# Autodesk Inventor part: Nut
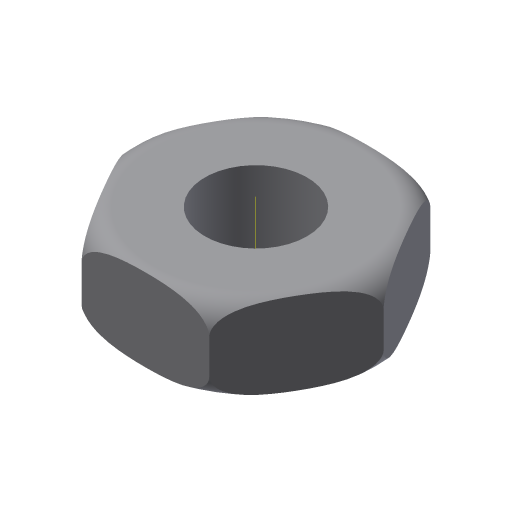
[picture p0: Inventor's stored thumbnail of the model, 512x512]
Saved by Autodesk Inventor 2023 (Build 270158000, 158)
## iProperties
Created: 2009-04
Part Number: Nut
Document SubType Name: Modeling
Designer: Sham
Density: 1 g/cm^3
Material: Generic
Appearance: Default
Author: Sham
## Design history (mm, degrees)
sketch "Sketch1"
  geometry: L1 (7.5, 12.99)-(15, 0); L2 (15, 0)-(7.5, -12.99); L3 (7.5, -12.99)-(-7.5, -12.99); L4 (-7.5, -12.99)-(-15, 0); L5 (-15, 0)-(-7.5, 12.99); L6 (-7.5, 12.99)-(7.5, 12.99); C1 r 6 at (0, 0); 1 further point
  constraints: 12 end point, 1 centre point, 1 coincident, 13 other
  dimensions: "d0" = 30 distance of L1.end L4.end; "d1" = 12 diameter of C1
extrude "Extrusion1" new body sketch "Sketch1" distance "d2" = 12; taper "d3" = 0 deg
sketch "Sketch2"
  geometry: L1 (-12, 0)-(-12, -0.022); L2 (-15, 7)-(-15, 3); L3 (0, -2.87)-(0, 12.87) reference; A1 r 3 centre (-12, 7) between (-12, 10) and (-15, 7); A2 r 3 centre (-12, 3) between (-15, 3) and (-12, 0)
  constraints: 4 end point, 4 point on circle, 2 centre point, 1 tangent
revolve "Revolution1" sketch "Sketch2" stored, may be unused: angle "d7" = 90 deg
body "Solid1"
other parameters: "d6" = 90 deg
